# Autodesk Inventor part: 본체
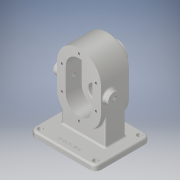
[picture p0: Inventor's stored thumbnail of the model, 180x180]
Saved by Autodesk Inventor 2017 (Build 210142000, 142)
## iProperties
Part Number: 본체
Material: 알루미늄 6061
Document SubType Name: Modeling
Designer: 00-00
Mass: 1440.46 g
Surface Area: 785.636 cm^2
Volume: 533.505 cm^3
Density: 2.7 g/cm^3
Appearance: 알루미늄 - 평지
Author: 00-00
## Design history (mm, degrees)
sketch "스케치1"
  geometry: L1 (0, 22)-(0, -22); L2 (-40, 22)-(-40, -22); L3 (40, -22)-(40, 22); L4 (-60, -80)-(60, -80); L5 (60, -80)-(60, -90); L6 (60, -90)-(-60, -90); L7 (-60, -90)-(-60, -80); A1 r 40 centre (0, 22) between (40, 22) and (-40, 22); A2 r 40 centre (0, -22) between (-40, -22) and (40, -22); 3 further points
  constraints: 16 end point, 4 point on circle, 4 tangent, 3 parallel, 2 centre point, 2 midpoint, 1 coincident, 1 horizontal, 1 perpendicular, 1 vertical, 1 vertical alignment
  dimensions: "d0" = 44 distance of L1.start L1.end; "d2" = 40 radius of A1; "d65" = 10 distance of L6.end L4.start; "d66" = 90 distance from line of point (0, 0) L6; "d67" = 120 distance of L5.end L6.end
extrude "돌출1" new body sketch "스케치1" distance "d3" = 14; taper "d5" = 0 deg; dims "d4" = 39, "d6" = 0
sketch "스케치2"
  geometry: L1 (0, 22)-(0, -22); L2 (-24, 22)-(-24, -22); L3 (24, -22)-(24, 22); A1 r 24 centre (0, 22) between (24, 22) and (-24, 22); A2 r 24 centre (0, -22) between (-24, -22) and (24, -22); 2 further points
  constraints: 8 end point, 4 point on circle, 4 tangent, 2 centre point, 1 coincident, 1 midpoint, 1 parallel, 1 vertical
  dimensions: "d7" = 44 distance of L1.start L1.end; "d8" = 24 radius of A1
extrude "돌출2" cut sketch "스케치2" distance "d9" = 29; taper "d10" = 0 deg
sketch "스케치3"
  geometry: C1 r 19 at (0, 22); A1 r 40 centre (0, 22) between (40, 22) and (-40, 22) reference; 1 further point
  constraints: 1 centre point, 1 coincident
  dimensions: "d11" = 38 diameter of C1
extrude "돌출3" join sketch "스케치3" distance "d12" = 17; taper "d13" = 0 deg
fillet "모깎기1" dims "d14" = 3
sketch "스케치4"
  geometry: C1 r 12.5 at (0, 22); C2 r 12.5 at (0, -22); A1 r 24 centre (0, 22) between (24, 22) and (-24, 22) reference; A2 r 24 centre (0, -22) between (-24, -22) and (24, -22) reference; 1 further point
  constraints: 2 centre point, 2 coincident, 1 equal radius
  dimensions: "d15" = 25 diameter of C1
extrude "돌출4" cut sketch "스케치4" distance "d16" = 15; taper "d17" = 0 deg
sketch "스케치5"
  geometry: C1 r 19 at (0, 0) reference; 1 further point
hole "구멍1" sketch "스케치5" at (0, 0) diameter "d18" = 17; stored, may be unused: countersink angle "d22" = 90 deg, drill point angle "d24" = 118 deg; dims "d19" = 6, "d20" = 28, "d21" = 7.3, "d23" = 8
fillet "모깎기2" dims "d25" = 0.5
chamfer "모따기1" distance "d26" = 0.7; stored, may be unused: second distance "d27" = 2, angle "d28" = 30 deg
sketch "스케치6"
  geometry: C1 r 12.5 at (0, 22) reference; C2 r 12.5 at (0, -22) reference; 3 further points
  constraints: 2 horizontal alignment
  dimensions: "d29" = 31 distance of C1.centre point (31, 22); "d30" = 31 distance of point (-31, -22) C2.centre
hole "구멍2" sketch "스케치6" diameter "d31" = 4.134; stored, may be unused: countersink angle "d35" = 90 deg, drill point angle "d37" = 118 deg; dims "d32" = 10, "d33" = 28, "d34" = 7.3, "d36" = 12
hole "구멍3" sketch "스케치6" diameter "d38" = 4.134; stored, may be unused: countersink angle "d42" = 90 deg, drill point angle "d44" = 118 deg; dims "d39" = 10, "d40" = 28, "d41" = 7.3, "d43" = 12
chamfer "모따기2" distance "d51" = 1; stored, may be unused: second distance "d52" = 2, angle "d53" = 30 deg
sketch "스케치7"
  geometry: C1 r 11 at (14, 22); 1 further point
  constraints: 1 centre point, 1 coincident
  dimensions: "d54" = 22 diameter of C1
extrude "돌출5" join sketch "스케치7" distance "d55" = 10; taper "d56" = 0 deg
sketch "스케치8"
  geometry: 1 further point
hole "구멍4" sketch "스케치8" at (0, 0) diameter "d58" = 8.376; stored, may be unused: countersink angle "d62" = 90 deg, drill point angle "d64" = 118 deg; dims "d59" = 20, "d60" = 28, "d61" = 7.3, "d63" = 27.3
fillet "모깎기3" dims "d57" = 3
extrude "돌출6" join sketch "스케치1" distance "d68" = 44; taper "d70" = 0 deg; dims "d69" = 56, "d71" = 0
fillet "모깎기4" dims "d72" = 10
sketch "스케치9"
  geometry: A1 r 10 centre (0, 10) between (-10, 10) and (0, 0) reference; A2 r 10 centre (0, 90) between (0, 100) and (-10, 90) reference; A3 r 10 centre (100, 90) between (110, 90) and (100, 100) reference; A4 r 10 centre (100, 10) between (100, 0) and (110, 10) reference; 1 further point
hole "구멍5" sketch "스케치9" at (0, 90), (100, 90), (100, 10), (0, 10) diameter "d73" = 9; stored, may be unused: countersink angle "d77" = 90 deg, drill point angle "d79" = 118 deg; dims "d74" = 20, "d75" = 28, "d76" = 7.3, "d78" = 27.3
fillet "모깎기5" dims "d80" = 3
sketch "스케치10"
  geometry: L1 (10, 35)-(90, 35); L2 (90, 35)-(90, 72); L3 (90, 72)-(10, 72); L4 (10, 72)-(10, 35); L5 (10, 27)-(10, 80) reference; L6 (90, 80)-(90, 27) reference; L7 (100, 97)-(0, 97) reference; 1 further point
  constraints: 8 end point, 2 collinear, 2 parallel, 1 horizontal, 1 perpendicular
  dimensions: "d81" = 37 distance of L1.end L2.end; "d82" = 25 distance between parallel lines of L7 L3
extrude "돌출7" join sketch "스케치10" stored distance "d83" = 38; taper "d84" = 0 deg
fillet "모깎기6" dims "d85" = 3
fillet "모깎기7" dims "d86" = 3
sketch "스케치11"
  geometry: L1 (0, -3)-(100, -3) reference; L2 (-10, 87)-(-10, 7) reference; 2 further points
  constraints: 1 other
  dimensions: "d87" = 12 distance from line of L1 point (50, 9); "d88" = 60 distance from line of L2 point (50, 9)
feature "엠보싱1" sketch "스케치11" dims "d0" = 44, "d2" = 40, "d65" = 10, "d66" = 90, "d67" = 120, "d89" = 0.5, "d90" = 0
node "솔리드1"
pattern_circular "원형 패턴1" dims angle "d46" = 180 deg
pattern_circular "원형 패턴2" dims angle "d49" = 180 deg
mirror "미러1"
